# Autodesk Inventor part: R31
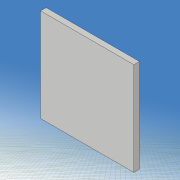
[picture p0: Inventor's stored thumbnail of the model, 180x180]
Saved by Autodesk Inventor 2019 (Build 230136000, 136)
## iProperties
Created: 2021-05
Part Number: R31
Material: 一般
Document SubType Name: Modeling
Designer: kikut
Density: 1 g/cm^3
Appearance: 既定
Mass: 0.0401953 g
Surface Area: 1.53643 cm^2
Volume: 0.0401953 cm^3
Author: kikut
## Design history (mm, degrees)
sketch "スケッチ1"
  geometry: L1 (80, 60)-(-80, 60); L2 (-80, 60)-(-80, -60); L3 (-80, -60)-(80, -60); L4 (80, -60)-(80, 60); L5 (80, 60)-(-80, -60); L6 (-80, 60)-(80, -60); 1 further point
  constraints: 12 end point, 2 midpoint, 2 parallel, 1 horizontal, 1 perpendicular
  dimensions: "d0" = 160 distance of L2.end L3.end; "d1" = 120 distance of L1.end L2.end
extrude "押し出し1" new body sketch "スケッチ1" stored distance "d2" = 0.6; taper "d3" = 0 deg
sketch "スケッチ2"
  geometry: L1 (-140, 0)-(140, 0) reference; L2 (0, -54)-(20, -30); L3 (0, 54)-(20, 30); L4 (0, -3)-(6.514, -3); L5 (6.514, -3)-(16, -6); L6 (16, -6)-(24, -3); L7 (24, -3)-(33.716, -3); L8 (0, 3)-(6.514, 3); L9 (6.514, 3)-(16, 6); L10 (16, 6)-(24, 3); L11 (24, 3)-(33.716, 3); L12 (0, -98)-(0, 98) reference; L13 (-100, -70)-(100, -70); L14 (100, -70)-(100, 70); L15 (100, 70)-(-100, 70); L16 (-100, 70)-(-100, -70); L17 (-100, -70)-(100, 70); L18 (100, -70)-(-100, 70); A1 r 60 centre (54.312, 28.5) between (0, 54) and (0, 3); A2 r 60 centre (54.312, -28.5) between (0, -3) and (0, -54); A3 r 18.111 centre (18, -12) between (20, -30) and (33.716, -3); A4 r 18.111 centre (18, 12) between (33.716, 3) and (20, 30); 1 further point
  constraints: 32 end point, 8 point on circle, 8 symmetric about line, 4 centre point, 3 horizontal, 2 collinear, 2 midpoint, 2 parallel, 1 perpendicular
  dimensions: "d5" = 60 radius of A1; "d6" = 6 distance of L8.start L4.start; "d7" = 108 distance of L3.start L2.start; "d8" = 0 horizontal distance of L3.start L8.start; "d9" = 60 distance of L3.end L2.end; "d10" = 0 horizontal distance of point (0, 0) L3.start; "d11" = 20 horizontal distance of L3.start L3.end; "d12" = 24 distance of A4.centre A3.centre; "d13" = 6 distance of L11.end L7.end; "d14" = 12 distance of L9.end L5.end; "d15" = 16 distance from line of L12 L5.end; "d16" = 24 distance from line of L6.end L12; "d17" = 200 distance of L14.end L15.end; "d18" = 140 distance of L15.end L13.start; "d30" = 18 distance from line of L12 A4.centre
extrude "押し出し2" cut sketch "スケッチ2" stored distance "d19" = 10; taper "d20" = 0 deg
sketch "スケッチ3"
  geometry: L1 (49.705, -17.97)-(33.948, -15.191); L2 (33.948, -15.191)-(34.295, -13.222); L3 (34.295, -13.222)-(50.052, -16); L4 (50.052, -16)-(49.705, -17.97); L5 (49.705, -17.97)-(34.295, -13.222); L6 (33.948, -15.191)-(50.052, -16); L7 (50.052, 16)-(34.295, 13.222); L8 (34.295, 13.222)-(33.948, 15.191); L9 (33.948, 15.191)-(49.705, 17.97); L10 (49.705, 17.97)-(50.052, 16); L11 (50.052, 16)-(33.948, 15.191); L12 (34.295, 13.222)-(49.705, 17.97); L13 (-112, 0)-(112, 0) reference; L14 (0, -84)-(0, 84) reference; 3 further points
  constraints: 24 end point, 4 midpoint, 4 parallel, 2 perpendicular, 2 symmetric about line
  dimensions: "d21" = 2 distance of L3.end L1.start; "d22" = 2 distance of L9.end L7.start; "d23" = 16 distance of L8.end L9.end; "d24" = 42 distance from line of L14 point (42, 15.596); "d26" = 10 deg angle of L7 L13; "d62" = 16 distance from line of L3.end L13
extrude "押し出し3" join sketch "スケッチ3" distance "d27" = 0.6; taper "d28" = 0 deg
fillet "フィレット1" dims "d31" = 2
fillet "フィレット2" dims "d32" = 1
sketch "スケッチ6"
  geometry: L1 (-20, 60)-(80, 60); L2 (80, 60)-(80, -60); L3 (80, -60)-(-20, -60); L4 (-20, -60)-(-20, 60); L5 (-46.168, 0)-(93.832, 0) reference; L6 (0, -84)-(0, 84) reference; L7 (20, 10)-(30, 10); L8 (30, 10)-(30, 20); L9 (30, 20)-(20, 20); L10 (20, 20)-(20, 10); 1 further point
  constraints: 16 end point, 4 parallel, 2 horizontal, 2 perpendicular, 1 other
  dimensions: "d63" = 120 distance of L3.end L1.start; "d64" = 100 distance of L1.start L1.end; "d65" = 20 distance between parallel lines of L6 L4; "d66" = 10 distance of L8.end L9.end; "d73" = 10 distance of L9.end L7.start; "d74" = 10 distance between parallel lines of L7 L5; "d75" = 40 distance between parallel lines of L10 L4
extrude "押し出し4" cut sketch "スケッチ6" stored distance "d70" = 10; taper "d71" = 0 deg
node "ソリッド1"
